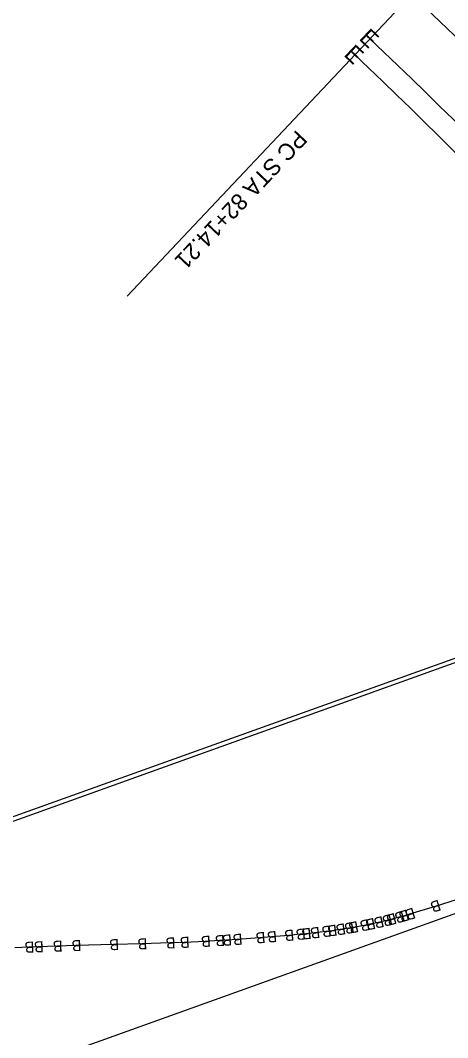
# Model space of a CAD drawing. Extents: x 74655 to 77873, y 48844 to 50507.
# Drawn here: x 74984.6 to 75061.9, y 49681 to 49865.1 of the extents above; entities that cross this region are included whole.
import ezdxf

# ---------------------------------------------------------------- set-up
doc = ezdxf.new("R2010")
doc.units = 0
for name, color, linetype in [('14', 7, 'Continuous'), ('2', 7, 'Continuous'), ('33', 7, 'Continuous'), ('6', 7, 'Continuous'), ('61', 7, 'Continuous'), ('7', 7, 'Continuous')]:
    doc.layers.add(name, color=color, linetype=linetype)

msp = doc.modelspace()

# ---------------------------------------------------------------- linework, layer by layer
at = {"layer": '14'}
for p, q in [((75068.8, 49707.63), (75059.62, 49704.76)), ((75059.62, 49704.76), (75055.01, 49703.34)), ((75053.14, 49702.8), (75051.63, 49702.4)), ((75053.89, 49703.01), (75053.14, 49702.8)), ((75055.01, 49703.34), (75053.89, 49703.01)), ((75044, 49700.83), (75042.46, 49700.59)), ((75044.77, 49700.95), (75044, 49700.83)), ((75046.81, 49701.33), (75044.77, 49700.95)), ((75047.83, 49701.53), (75046.81, 49701.33)), ((75049.36, 49701.85), (75047.83, 49701.53)), ((75050.88, 49702.21), (75049.36, 49701.85)), ((75051.63, 49702.4), (75050.88, 49702.21)), ((75027.93, 49699.09), (75023.77, 49698.78)), ((75030.01, 49699.25), (75027.93, 49699.09)), ((75033.13, 49699.51), (75030.01, 49699.25)), ((75035.21, 49699.71), (75033.13, 49699.51)), ((75036.25, 49699.81), (75035.21, 49699.71)), ((75037.8, 49699.98), (75036.25, 49699.81)), ((75039.87, 49700.23), (75037.8, 49699.98)), ((75040.91, 49700.37), (75039.87, 49700.23)), ((75042.46, 49700.59), (75040.91, 49700.37)), ((74986.11, 49697.38), (74983.56, 49697.27)), ((74987.81, 49697.45), (74986.11, 49697.38)), ((74991.22, 49697.56), (74987.81, 49697.45)), ((74994.62, 49697.66), (74991.22, 49697.56)), ((75001.44, 49697.84), (74994.62, 49697.66)), ((75006.54, 49697.98), (75001.44, 49697.84)), ((75011.65, 49698.14), (75006.54, 49697.98)), ((75014.21, 49698.24), (75011.65, 49698.14)), ((75018.03, 49698.42), (75014.21, 49698.24)), ((75020.59, 49698.57), (75018.03, 49698.42)), ((75021.86, 49698.65), (75020.59, 49698.57)), ((75023.77, 49698.78), (75021.86, 49698.65))]:
    msp.add_line(p, q, dxfattribs=at)
at = {"layer": '2'}
for radius in [818.51, 807.51, 803.51]:
    msp.add_arc((74494, 49274.13), radius, 30.80505, 46.69786, dxfattribs=at)
at = {"layer": '33'}
msp.add_lwpolyline([(75055.37, 49869.8), (75003.93, 49815.22)], dxfattribs=at)
at = {"layer": '6'}
msp.add_line((74978.35, 49673.03), (75354.83, 49808.15), dxfattribs=at)
at = {"layer": '7'}
for p, q in [((74963.65, 49713.97), (75340.14, 49849.09)), ((74963.91, 49713.27), (75340.39, 49848.38))]:
    msp.add_line(p, q, dxfattribs=at)

# ---------------------------------------------------------------- texts
at = {"layer": '2'}
for p in [(75045.71, 49861.73), (75042.97, 49858.82)]:
    msp.add_text('E', height=3, rotation=316.6979, dxfattribs=at).set_placement(p)
at = {"layer": '33'}
msp.add_text('PC STA 82+14.21', height=3, rotation=226.6979, dxfattribs=at).set_placement((75034.55, 49845.47))
at = {"layer": '61'}
for rotation, p in [(197.1516, (75055.68, 49704.59)), (197.3293, (75060.27, 49706.02)), (192.062, (75048.6, 49702.71)), (193.1344, (75050.11, 49703.05)), (193.9814, (75051.61, 49703.42)), (194.8707, (75052.34, 49703.62)), (195.7934, (75053.83, 49704.03)), (196.5934, (75054.57, 49704.25)), (185.7959, (75036.1, 49700.8)), (186.2105, (75037.13, 49700.91)), (186.87, (75038.68, 49701.09)), (187.5032, (75040.74, 49701.35)), (188.0878, (75041.76, 49701.5)), (188.8504, (75043.29, 49701.73)), (189.4654, (75044.82, 49701.98)), (190.2766, (75045.57, 49702.12)), (191.2191, (75047.6, 49702.5)), (181.5395, (75002.41, 49698.86)), (181.8675, (75007.51, 49699.01)), (182.2677, (75012.61, 49699.18)), (182.7169, (75015.16, 49699.29)), (183.2562, (75018.98, 49699.48)), (183.6259, (75021.52, 49699.63)), (183.9629, (75022.79, 49699.72)), (184.1947, (75024.7, 49699.85)), (184.4024, (75028.85, 49700.16)), (184.7975, (75030.92, 49700.33)), (185.3657, (75034.03, 49700.6)), (182.2188, (74987.07, 49698.42)), (181.9441, (74988.78, 49698.48)), (181.6693, (74992.19, 49698.59)), (181.4765, (74995.6, 49698.69))]:
    msp.add_text('B', height=2, rotation=rotation, dxfattribs=at).set_placement(p)

doc.saveas('drawing.dxf')
